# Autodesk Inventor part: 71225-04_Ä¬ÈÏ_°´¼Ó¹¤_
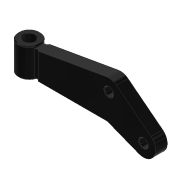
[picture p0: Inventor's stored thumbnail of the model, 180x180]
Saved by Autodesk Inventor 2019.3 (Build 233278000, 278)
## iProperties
Created: 2010-06
Part Number: 71225-04_Ä¬ÈÏ_°´¼Ó¹¤_
Material: Ogólny
Document SubType Name: Modeling
Designer: CADENGINEERING4
Density: 1 g/cm^3
Appearance: Gładki — czarny
Author: CADENGINEERING4
Revision Number: ÈÎºÎ
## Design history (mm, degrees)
feature "NONE"
feature "NONE:1"
feature "NONE:2"
feature "NONE:3"
node "Bryła1"
node "Bryła2"
node "Bryła3"
node "Bryła4"
